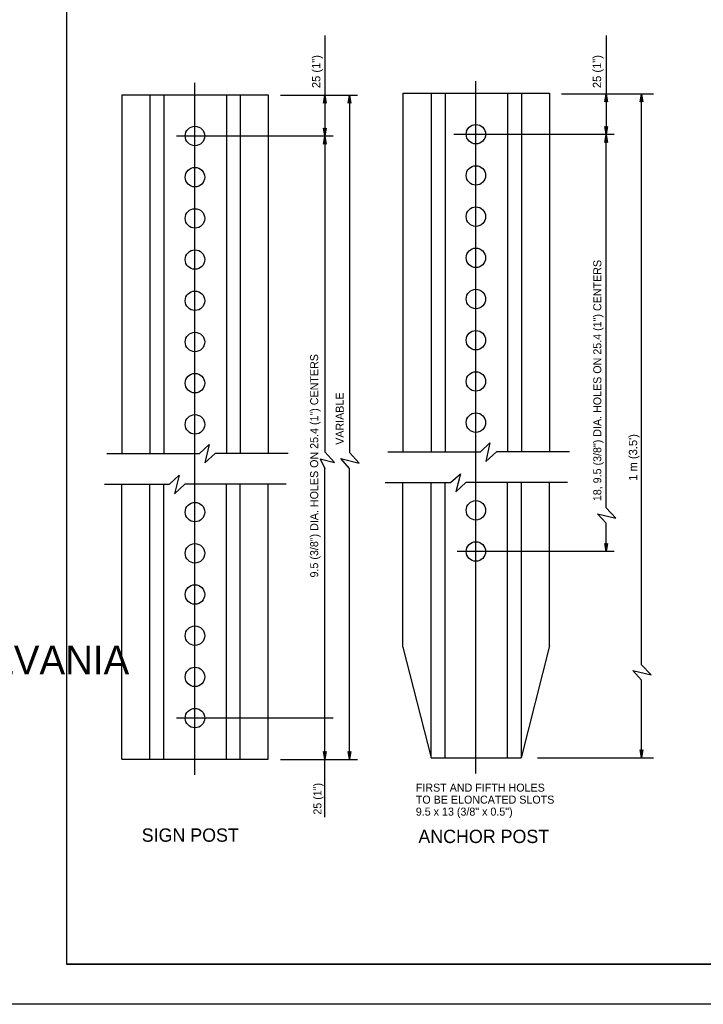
# Model space of a CAD drawing. Extents: x 644358 to 648627, y 294594 to 295782.
# Drawn here: x 647744.8 to 648001.1, y 295187.6 to 295556.9 of the extents above; entities that cross this region are included whole.
import ezdxf

# ---------------------------------------------------------------- set-up
doc = ezdxf.new("R2010")
doc.units = 0
for name, color, linetype in [('1', 7, 'Continuous'), ('2', 7, 'Continuous'), ('3', 7, 'Continuous'), ('4', 7, 'Continuous'), ('PLT-BNDY', 7, 'Continuous')]:
    doc.layers.add(name, color=color, linetype=linetype)

# ---------------------------------------------------------------- blocks, each defined once
blk = doc.blocks.new('RARROW')
at = {"layer": '3'}
blk.add_lwpolyline([(-2.2695, 0.285), (-2.184875, 0.12075), (0, 0), (-2.2695, 0.285), (-2.38575, 0.384625), (0, 0), (-2.183125, -0.108), (-2.262875, -0.2705), (0, 0), (-2.38575, -0.379125), (-2.262875, -0.2705)], dxfattribs=at)

msp = doc.modelspace()

# ---------------------------------------------------------------- linework, layer by layer
at = {"layer": '1'}
for p, q in [((647762.31, 295766.63), (647762.31, 295202.63)), ((648548.31, 295202.63), (647762.31, 295202.63)), ((647762.31, 295202.63), (648348.31, 295202.63))]:
    msp.add_line(p, q, dxfattribs=at)
at = {"layer": '2'}
for p, q in [((647783.15, 295528.71), (647838.03, 295528.71)), ((647783.15, 295528.71), (647783.15, 295394.21)), ((647793.65, 295528.71), (647793.65, 295394.21)), ((647798.9, 295528.71), (647798.9, 295394.21)), ((647822.4, 295528.71), (647822.4, 295394.21)), ((647827.53, 295528.71), (647827.53, 295394.21)), ((647838.03, 295528.71), (647838.03, 295394.21)), ((647888.53, 295529.33), (647943.4, 295529.33)), ((647888.53, 295529.33), (647888.53, 295394.83)), ((647899.03, 295529.33), (647899.03, 295394.83)), ((647904.28, 295529.33), (647904.28, 295394.83)), ((647927.65, 295529.33), (647927.65, 295394.83)), ((647932.9, 295529.33), (647932.9, 295394.83)), ((647943.4, 295529.33), (647943.4, 295394.83)), ((647917.65, 295394.83), (647921.15, 295398.21)), ((647921.15, 295398.21), (647919.53, 295391.21)), ((647777.53, 295394.21), (647812.28, 295394.21)), ((647812.28, 295394.21), (647815.9, 295397.58)), ((647815.9, 295397.58), (647814.28, 295390.71)), ((647814.28, 295390.71), (647818.15, 295394.21)), ((647845.53, 295394.21), (647818.15, 295394.21)), ((647882.9, 295394.83), (647917.65, 295394.83)), ((647919.53, 295391.21), (647923.53, 295394.83)), ((647950.9, 295394.83), (647923.53, 295394.83)), ((647801.03, 295382.71), (647804.65, 295386.08)), ((647804.65, 295386.08), (647802.9, 295379.08)), ((647881.9, 295383.33), (647906.28, 295383.33)), ((647888.53, 295321.58), (647888.53, 295383.33)), ((647899.03, 295280.08), (647899.03, 295383.33)), ((647904.28, 295280.08), (647904.28, 295383.33)), ((647906.28, 295383.33), (647910.03, 295386.58)), ((647910.03, 295386.58), (647908.28, 295379.83)), ((647908.28, 295379.83), (647912.15, 295383.33)), ((647950.15, 295383.33), (647912.15, 295383.33)), ((647927.65, 295280.08), (647927.65, 295383.33)), ((647932.9, 295280.08), (647932.9, 295383.33)), ((647943.4, 295322.08), (647943.4, 295383.33)), ((647776.65, 295382.71), (647801.03, 295382.71)), ((647783.15, 295279.58), (647783.15, 295382.71)), ((647793.65, 295279.58), (647793.65, 295382.71)), ((647798.9, 295279.58), (647798.9, 295382.71)), ((647802.9, 295379.08), (647806.78, 295382.71)), ((647844.78, 295382.71), (647806.78, 295382.71)), ((647822.4, 295279.58), (647822.4, 295382.71)), ((647827.53, 295279.58), (647827.53, 295382.71)), ((647838.03, 295279.58), (647838.03, 295382.71)), ((647888.53, 295321.58), (647899.03, 295280.08)), ((647943.4, 295322.08), (647932.78, 295280.08)), ((647783.15, 295279.58), (647838.03, 295279.58)), ((647899.03, 295280.08), (647932.78, 295280.08))]:
    msp.add_line(p, q, dxfattribs=at)
for centre in [(647810.52, 295513.24), (647915.86, 295513.91), (647810.52, 295497.79), (647915.86, 295498.46), (647915.86, 295483.01), (647810.52, 295482.34), (647810.52, 295466.9), (647915.86, 295467.56), (647810.52, 295451.45), (647915.86, 295452.11), (647810.52, 295436), (647915.86, 295436.66), (647810.52, 295420.55), (647915.86, 295421.21), (647810.52, 295405.1), (647915.86, 295405.76), (647810.52, 295372.2), (647915.86, 295372.87), (647915.86, 295357.42), (647810.52, 295356.75), (647810.52, 295341.3), (647810.52, 295325.86), (647810.52, 295310.41), (647810.52, 295294.96)]:
    msp.add_circle(centre, 3.65, dxfattribs=at)
at = {"layer": '4'}
for p, q in [((647859.28, 295550.91), (647859.28, 295513.21)), ((647964.65, 295550.91), (647964.65, 295513.83)), ((647810.53, 295273.71), (647810.53, 295533.21)), ((647915.9, 295274.21), (647915.9, 295533.83)), ((647842.65, 295528.58), (647871.53, 295528.58)), ((647868.53, 295528.58), (647868.53, 295394.56)), ((647947.9, 295529.08), (647982.4, 295529.08)), ((647977.9, 295314.96), (647977.9, 295529.08)), ((647862.4, 295513.21), (647803.65, 295513.21)), ((647859.28, 295513.21), (647859.28, 295394.78)), ((647967.65, 295513.83), (647907.65, 295513.83)), ((647964.65, 295373.78), (647964.65, 295513.83)), ((647862.9, 295390.78), (647859.28, 295394.78)), ((647872.15, 295390.56), (647868.53, 295394.56)), ((647857.51, 295392.21), (647862.9, 295390.78)), ((647857.51, 295392.21), (647859.28, 295388.61)), ((647865.28, 295392.31), (647872.15, 295390.56)), ((647868.53, 295388.56), (647865.28, 295392.31)), ((647859.28, 295257.79), (647859.28, 295388.61)), ((647868.53, 295279.46), (647868.53, 295388.56)), ((647968.28, 295369.9), (647964.65, 295373.78)), ((647961.4, 295371.53), (647968.28, 295369.9)), ((647964.65, 295368.03), (647961.4, 295371.53)), ((647964.65, 295357.46), (647964.65, 295368.03)), ((647967.65, 295357.46), (647908.9, 295357.46)), ((647977.9, 295309.21), (647974.65, 295312.83)), ((647974.65, 295312.83), (647981.53, 295311.21)), ((647981.53, 295311.21), (647977.9, 295314.96)), ((647977.9, 295280.08), (647977.9, 295309.21)), ((647862.4, 295294.96), (647803.65, 295294.96)), ((647938.9, 295280.08), (647982.4, 295280.08)), ((647842.65, 295279.46), (647871.53, 295279.46))]:
    msp.add_line(p, q, dxfattribs=at)
at = {"layer": 'PLT-BNDY'}
msp.add_lwpolyline([(647722.31, 295781.63), (648563.31, 295781.63), (648563.31, 295187.63), (647722.31, 295187.63)], close=True, dxfattribs=at)

# ---------------------------------------------------------------- block references
at = {"layer": '2', "xscale": 1.2574347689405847, "yscale": 1.3092961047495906}
for p, rotation in [((647859.28, 295528.58), 89.99999999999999), ((647868.53, 295528.58), 89.99999999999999), ((647964.65, 295529.08), 89.99999999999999), ((647977.9, 295529.08), 89.99999999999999), ((647859.28, 295513.21), -90.00000000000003), ((647964.65, 295513.83), -90.00000000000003), ((647859.28, 295513.21), 89.99999999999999), ((647964.65, 295513.83), 89.99999999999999), ((647964.65, 295357.46), -90.00000000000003), ((647859.28, 295279.46), -90.00000000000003), ((647868.53, 295279.46), -90.00000000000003), ((647977.9, 295280.08), -90.00000000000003)]:
    msp.add_blockref('RARROW', p, dxfattribs=dict(at, rotation=rotation))

# ---------------------------------------------------------------- texts
at = {"layer": '1'}
msp.add_text('COMMONWEALTH OF PENNSYLVANIA', height=10.7828, dxfattribs=at).set_placement((647519.9, 295311.36))
at = {"layer": '4'}
for s, height, p in [('25 (1")', 3.125, (647857.54, 295531.2)), ('25 (1")', 3.125, (647962.83, 295531.2)), ('18, 9.5 (3/8") DIA. HOLES ON 25.4 (1") CENTERS', 3, (647962.88, 295376.3)), (' 9.5 (3/8") DIA. HOLES ON 25.4 (1") CENTERS', 3, (647856.73, 295346.57)), ('VARIABLE', 3, (647866.3, 295397.43)), ("1 m (3.5')", 3.125, (647976.34, 295383.95)), ('25 (1")', 3, (647857.94, 295258.75))]:
    msp.add_text(s, height=height, rotation=90, dxfattribs=at).set_placement(p)
for s, height, p in [('FIRST AND FIFTH HOLES ', 3, (647893.34, 295267.38)), ('TO BE ELONCATED SLOTS', 3, (647893.34, 295262.88)), ('9.5 x 13 (3/8" x 0.5")', 3, (647893.34, 295258.38)), ('SIGN POST', 5, (647790.57, 295248.58)), ('ANCHOR POST', 5, (647894.3, 295248.1))]:
    msp.add_text(s, height=height, dxfattribs=at).set_placement(p)

doc.saveas('drawing.dxf')
